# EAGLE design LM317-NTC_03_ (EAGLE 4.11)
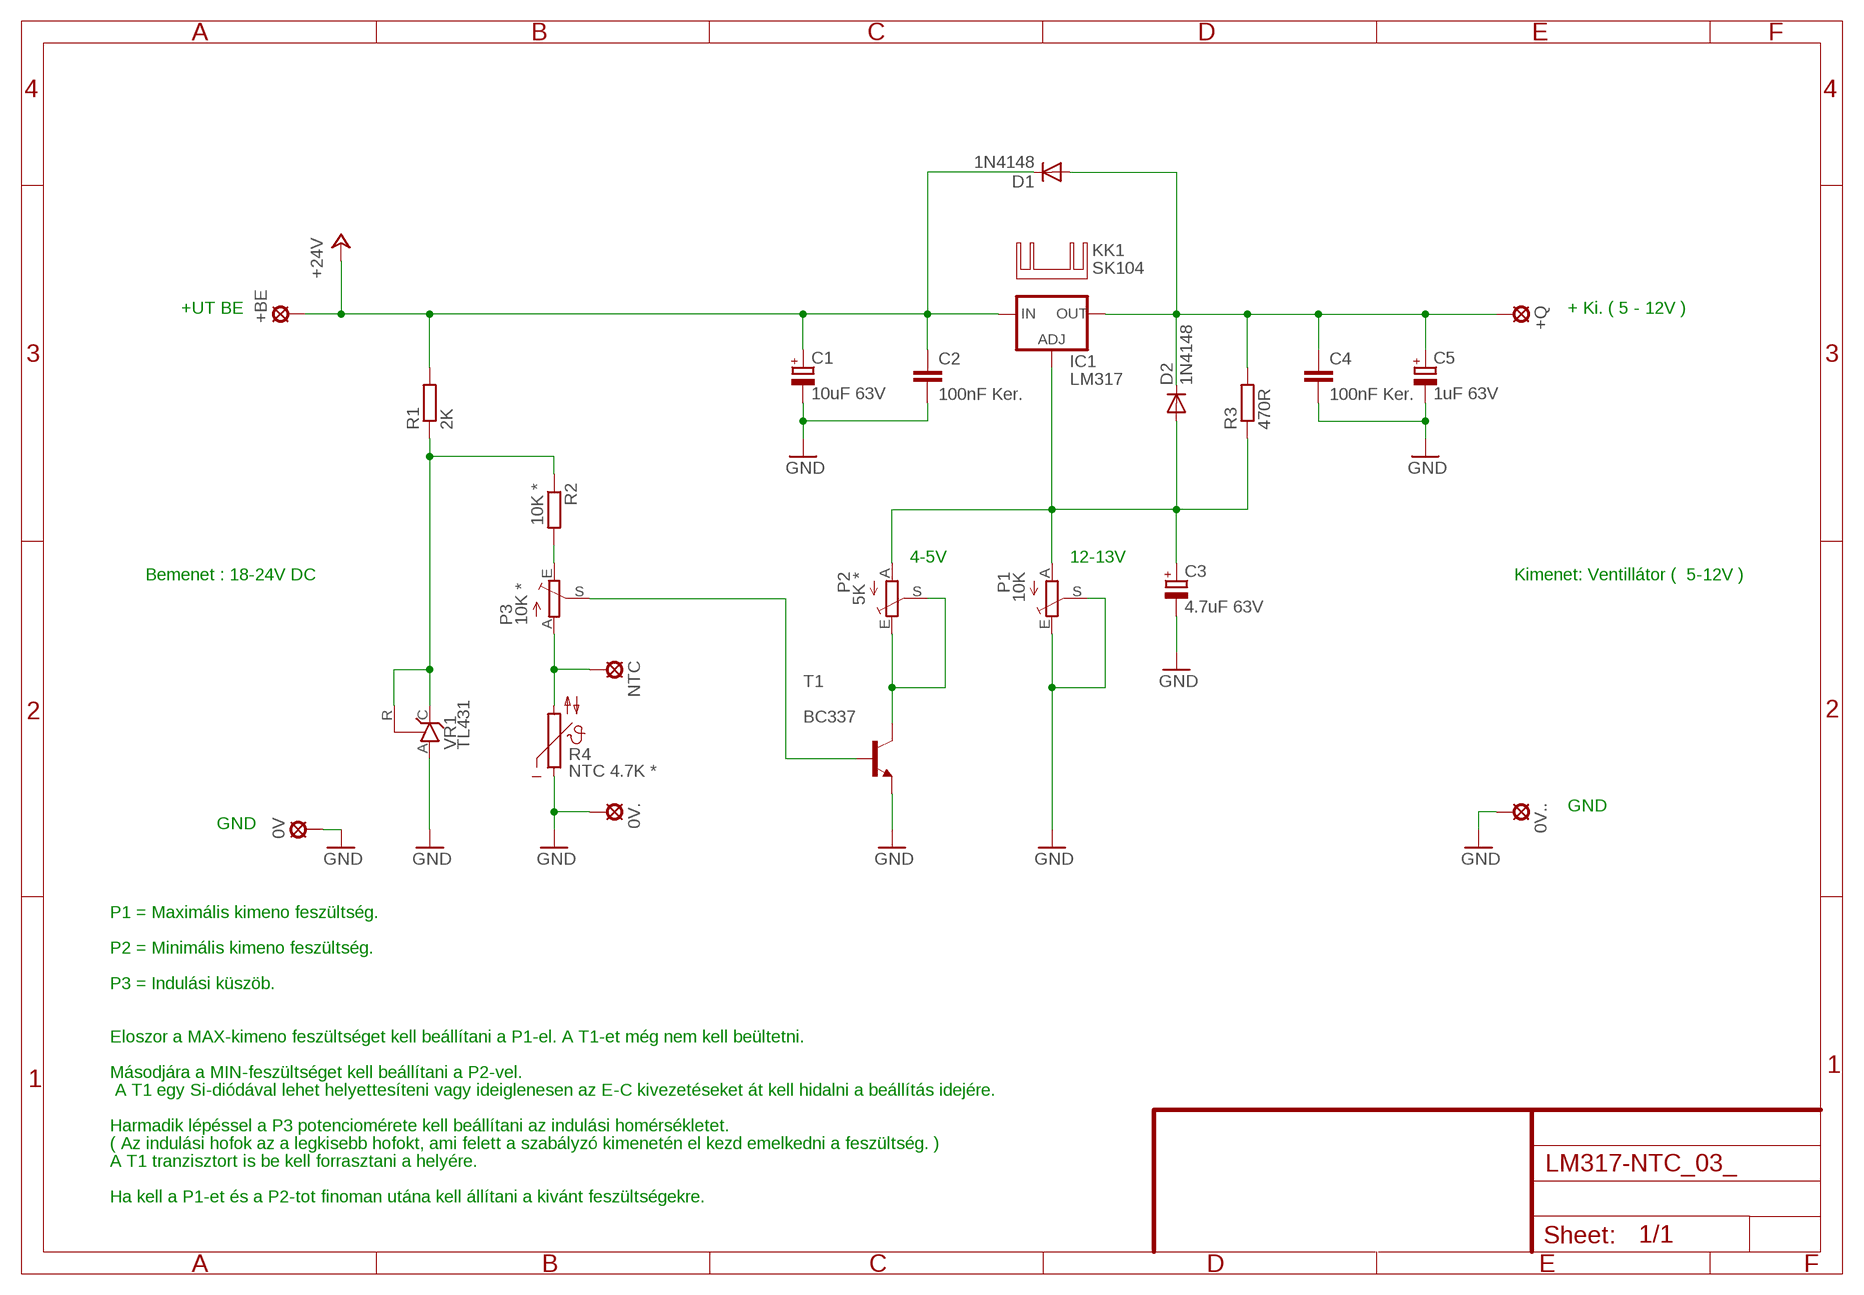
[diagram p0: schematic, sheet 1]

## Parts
0V  MCS10B  [MCS10B]
0V.  MCS10B  [MCS10B]
0V..  MCS10B  [MCS10B]
+BE  MCS10B  [MCS10B]
+Q  MCS10B  [MCS10B]
C1  10uF 63V  CPOL-EUE3.5-8  [E3,5-8]
C2  100nF Ker.  C-EU025-025X050  [C025-025X050]
C3  4.7uF 63V  CPOL-EUE3.5-8  [E3,5-8]
C4  100nF Ker.  C-EU025-025X050  [C025-025X050]
C5  1uF 63V  CPOL-EUE3.5-8  [E3,5-8]
D1  1N4148  [DO35-10]
D2  1N4148  [DO35-10]
IC1  LM317  LM317TS  [317TS]
KK1  SK104  [SK104]
NTC  MCS10B  [MCS10B]
P1  10K  TRIM_EU-B90P  [SP19L]
P2  5K *  TRIM_EU-B90P  [SP19L]
P3  10K *  TRIM_EU-B90P  [SP19L]
R1  2K  R-EU_0207/10  [0207/10]
R2  10K *  R-EU_0207/10  [0207/10]
R3  470R  R-EU_0207/10  [0207/10]
R4  NTC 4.7K *  NTC640-9  [N640]
T1  BC337  BC338-40-NPN-TO92-EBC  [TO92-EBC]
VR1  TL431  TL431CLP  [TO92-CLP]

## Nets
+24V: +BE.MP C1.+ C2.1 D1.C IC1.3(IN) R1.2
N$2: P3.E R2.2
N$3: NTC.MP P3.A R4.2
N$4: +Q.MP C4.1 C5.+ D1.A D2.C IC1.2(OUT) R3.2
N$5: P3.S T1.B
N$6: P2.E P2.S T1.C
N$7: C3.+ D2.A IC1.1(ADJ) P1.A P2.A R3.1
N$15: R1.1 R2.1 VR1.C VR1.R
N$16: 0V...MP 0V..MP 0V.MP C1.- C2.2 C3.- C4.2 C5.- P1.E P1.S R4.1 T1.E VR1.A ; supply symbol labelled GND

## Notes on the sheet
- +UT BE | + Ki. ( 5 - 12V )
- 4-5V | 12-13V
- Bemenet : 18-24V DC | Kimenet: Ventillátor (  5-12V )
- GND
- GND
- P1 = Maximális kimeno feszültség.
- P2 = Minimális kimeno feszültség.
- P3 = Indulási küszöb.
- Eloszor a MAX-kimeno feszültséget kell beállítani a P1-el. A T1-et még nem kell beültetni.
- Másodjára a MIN-feszültséget kell beállítani a P2-vel.
- A T1 egy Si-diódával lehet helyettesíteni vagy ideiglenesen az E-C kivezetéseket át kell hidalni a beállítás idejére.
- Harmadik lépéssel a P3 potenciomérete kell beállítani az indulási homérsékletet.
- ( Az indulási hofok az a legkisebb hofokt, ami felett a szabályzó kimenetén el kezd emelkedni a feszültség. )
- A T1 tranzisztort is be kell forrasztani a helyére.
- Ha kell a P1-et és a P2-tot finoman utána kell állítani a kivánt feszültségekre.

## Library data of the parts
0V 0V. 0V.. +BE +Q NTC = solpad:MCS10B: SOLDER PAD
C1 C3 C5 = rcl:CPOL-EU: POLARIZED CAPACITOR, European symbol
C2 C4 = rcl:C-EU: CAPACITOR, European symbol
D1 D2 = diode:1N4148: DIODE
IC1 = v-reg:LM317TS: VOLTAGE REGULATOR
KK1 = heatsink:SK104: HEATSINK
P1-P3 = pot:TRIM_EU-: POTENTIOMETER
R1-R3 = rcl:R-EU_: RESISTOR, European symbol
R4 = ptc-ntc:NTC640-9: PHILIPS NTC
T1 = transistor:*-NPN-: NPN Transistror
VR1 = v-reg:TL431CLP: VOLTAGE REGULATOR

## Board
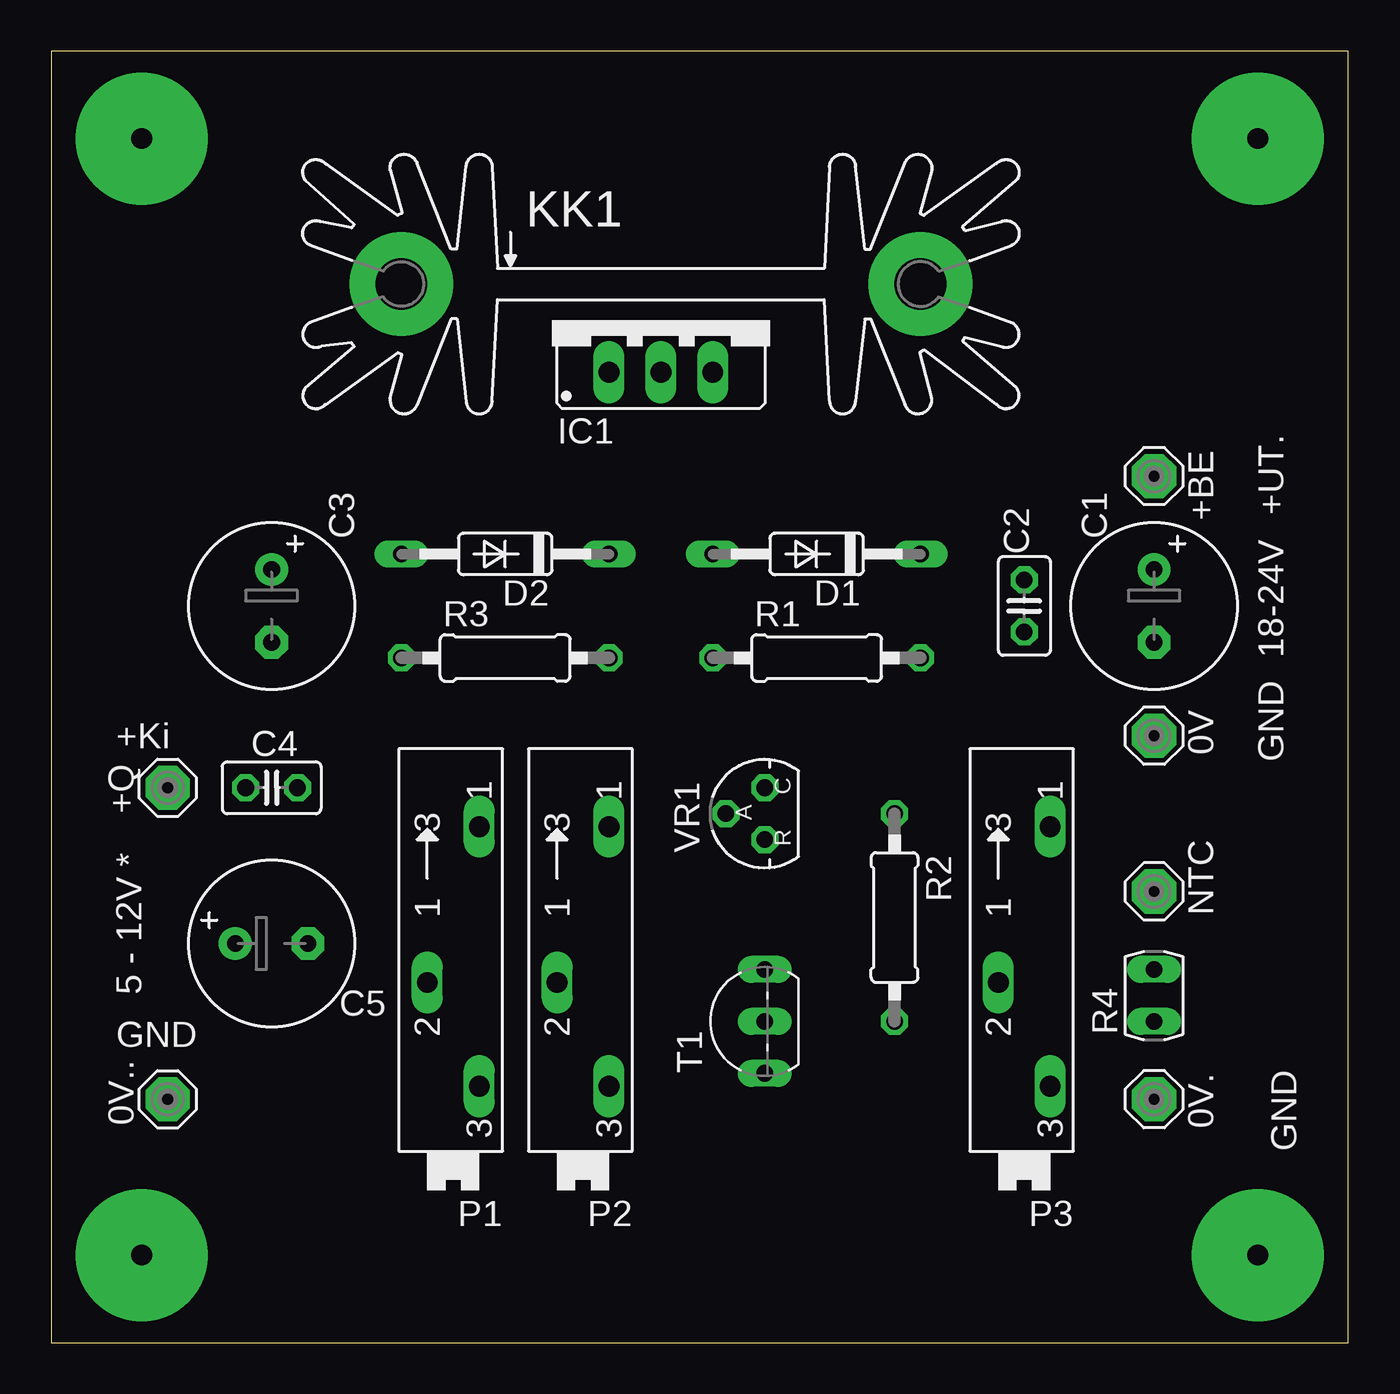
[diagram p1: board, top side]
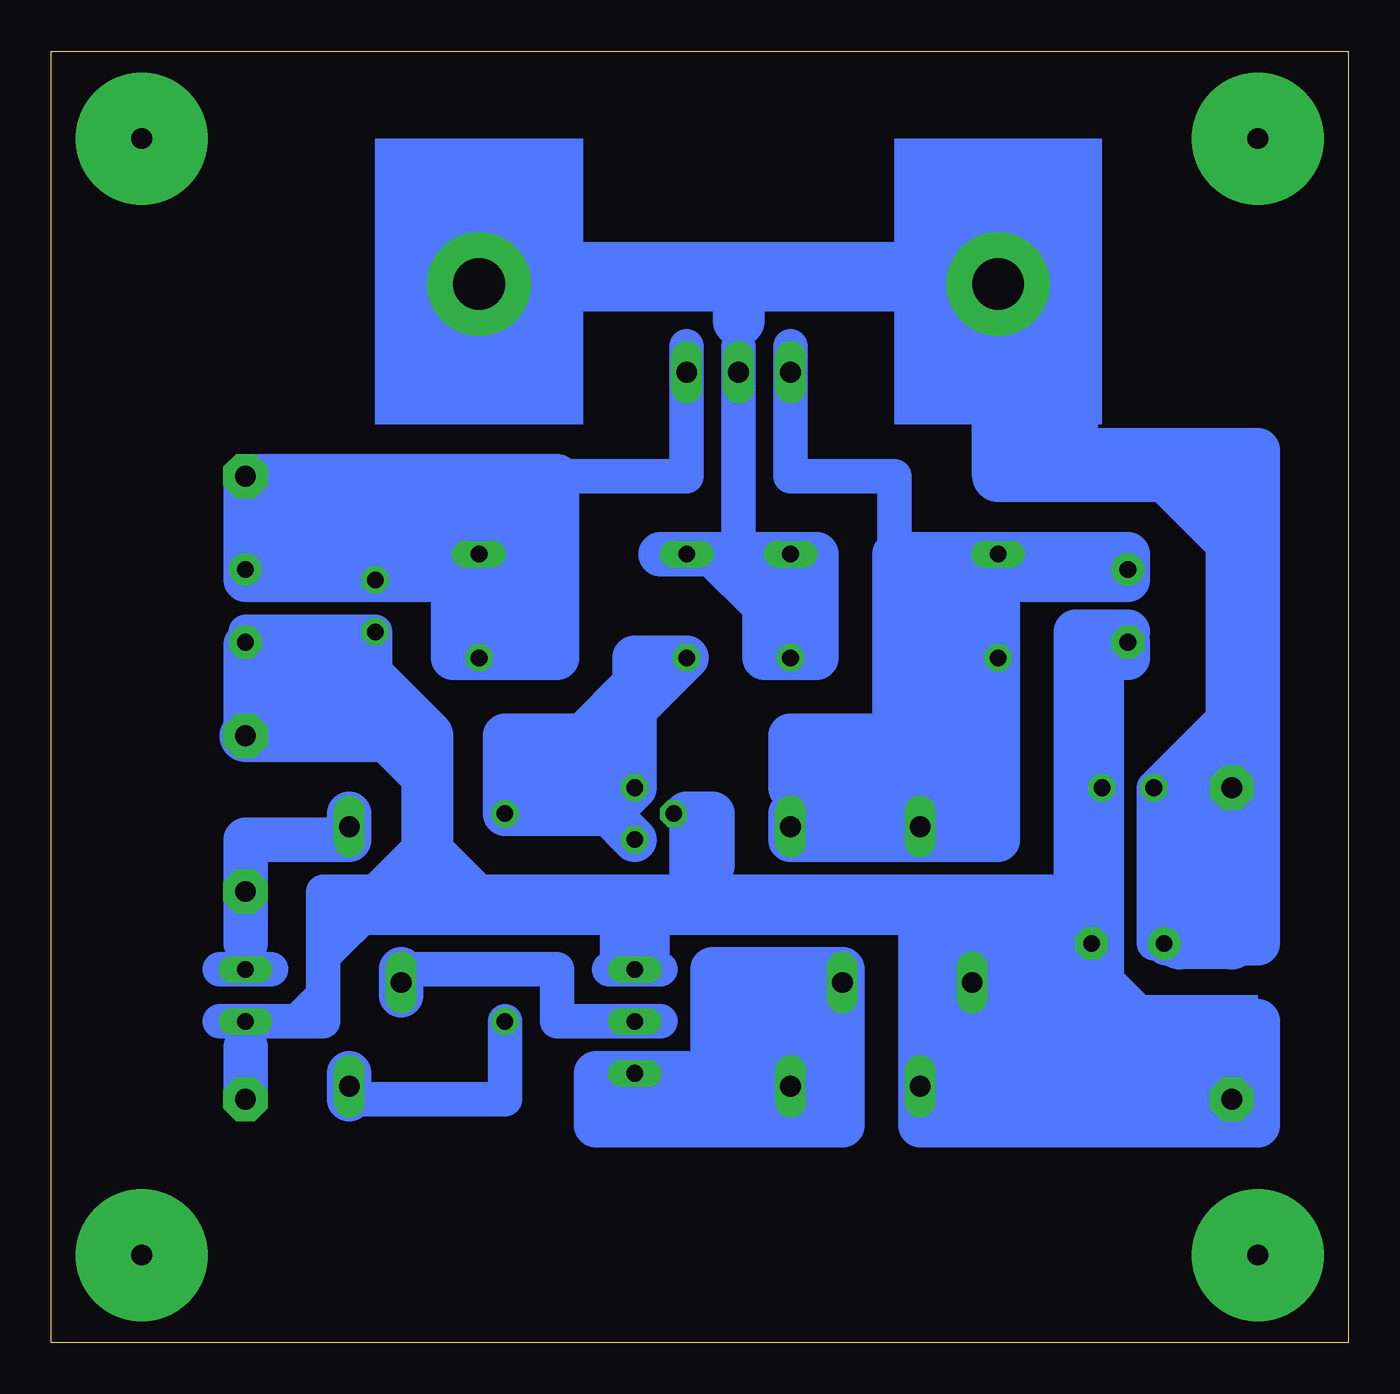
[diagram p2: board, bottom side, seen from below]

Size 63.48 x 63.17 mm. Coordinates in mm from the lower left corner, seen from the top.
Outline: 0,0 63.48,0 63.48,63.17 0,63.17 0,0
Copper layers (1*16): Top 0.035mm / dielectric 1.5mm / Bottom 0.035mm
Design rules "default": minimum track width 10mil, minimum drill 24mil, track to track 8mil, track to pad 8mil, pad to pad 8mil, via to via 8mil, smd to smd 8mil, copper to edge 40mil, drill to drill 8mil, minimum pad ring 10mil, minimum via ring 8mil, stop-mask expansion 4mil, vias tented up to drill 0mil, thermal gap 10mil

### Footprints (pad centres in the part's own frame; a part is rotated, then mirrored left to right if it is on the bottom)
MCS10B = drill 1.016 pad 2.159 octagon: MP 0,0
E3,5-8 = drill 0.813 pad 1.6 round: + -1.778,0 | drill 0.813 pad 1.6 octagon: - 1.778,0
C025-025X050 = drill 0.813 octagon: 1 -1.27,0; 2 1.27,0
DO35-10 = drill 0.813 long: A 5.08,0; C -5.08,0
317TS = drill 1.016 long: 1 -2.54,-2.54; 2 0,-2.54; 3 2.54,-2.54
SK104 = drill 2.54 pad 5.08 round: A2,5 -12.7,-0.762; B2,5 12.7,-0.762
SP19L = drill 1.016 long: A 5.715,-1.27; E -6.985,-1.27; S -1.905,1.27
0207/10 = drill 0.813 octagon: 1 -5.08,0; 2 5.08,0
N640 = drill 0.813 long: 1 -1.27,0; 2 1.27,0
TO92-EBC = drill 0.813 long: B 0,-1.27; C -2.54,-1.27; E 2.54,-1.27
TO92-CLP = drill 0.813 octagon: A 0,1.905; C 1.27,0; R -1.27,0

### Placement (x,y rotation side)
0V  53.97,29.68 270 top
0V.  53.97,11.9 270 top
0V..  5.71,11.9 90 top
+BE  53.97,42.38 270 top
+Q  5.71,27.14 90 top
C1  53.97,36.03 270 top
C2  47.62,36.03 270 top
C3  10.79,36.03 270 top
C4  10.79,27.14 0 top
C5  10.79,19.52 0 top
D1  37.46,38.57 180 top
D2  22.22,38.57 180 top
IC1  29.84,50 0 top
KK1  29.84,52.54 0 top
NTC  53.97,22.06 270 top
P1  19.68,19.52 90 top
P2  26.03,19.52 90 top
P3  47.62,19.52 90 top
R1  37.46,33.49 0 top
R2  41.27,20.79 270 top
R3  22.22,33.49 0 top
R4  53.97,16.98 90 top
T1  33.65,15.71 90 top
VR1  34.92,25.87 90 top

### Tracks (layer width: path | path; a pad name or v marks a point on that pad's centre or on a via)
+24V
  Bottom 0.406: 43.81,38.57 47.62,38.57 | 53.97,37.3 C1.+ 53.97,38.57
  Bottom 1.676: 32.38,48.73 IC1.3 32.38,42.38 38.73,42.38 | 41.27,42.38 42.54,42.38 42.54,41.11 D1.C | 43.81,38.57 D1.C | R1.2 42.54,37.3 | D1.C 47.62,38.57 | C2.1 47.62,38.57 | 47.62,38.57 53.97,38.57 | D1.C 42.54,37.3 | 42.54,37.3 53.97,37.3
  Bottom 2.184: R1.2 D1.C 41.27,38.57 | 41.27,42.38 +BE.MP 53.97,38.57 53.97,37.3 41.27,37.3 | 41.27,37.3 41.27,42.38 | 41.27,42.38 42.54,41.11 43.81,41.11 | 43.81,41.11 52.7,41.11 52.7,39.84 43.81,39.84 43.81,33.49 41.27,33.49 | 41.27,33.49 41.27,37.3 | 41.27,42.38 38.73,42.38 | 38.73,42.38 42.54,42.38 43.81,41.11 | 38.73,42.38 38.73,33.49 40,33.49 | 41.27,33.49 40,33.49 | 40,33.49 40,41.11
N$1
  Bottom 2.184: 34.28,20.15 34.28,18.88
N$2
  Bottom 0.406: 48.89,13.17 P3.E 48.89,11.9
  Bottom 1.676: R2.2 41.27,11.9 48.89,11.9
  Bottom 2.184: 48.89,13.17 48.89,11.9
N$3
  Bottom 0.406: P3.A 48.89,24.6
  Bottom 1.676: R4.2 52.7,18.25 | 55.24,18.25 R4.2 | R4.2 53.97,19.52 NTC.MP 53.97,24.6 50.16,24.6
  Bottom 2.184: 48.89,25.87 48.89,24.6 | 50.16,24.6 48.89,24.6 | 48.89,24.6 53.97,24.6 53.97,19.52
N$4
  Bottom 0.406: IC1.2 29.84,38.57 D1.A | D2.C R3.2 | 17.14,52.54 29.84,52.54 | 29.84,50 29.84,48.73
  Bottom 1.676: 4.44,28.41 4.44,27.14 | 4.44,27.14 4.44,25.87 | 4.44,19.52 4.44,27.14 | 4.44,27.14 4.44,43.65 | 15.87,43.65 15.87,44.92 | 29.84,38.57 D2.C R3.2 | 29.84,38.57 33.65,38.57 | IC1.2 29.84,48.73 29.84,38.57 | +Q.MP C4.1 | 9.52,19.52 C5.+ | C4.1 9.52,19.52 | 5.71,30.95 8.25,28.41 | 8.25,28.41 C4.1 | 6.98,28.41 8.25,28.41 | 5.71,19.52 8.88,19.52 9.52,19.52 | 9.52,42.38 5.71,38.57 5.71,39.84 8.25,42.38
  Bottom 2.184: 15.87,43.65 4.44,43.65 4.44,19.52 8.88,19.52 | D2.C 33.65,38.57 31.11,38.57 28.57,36.03 | D2.C 26.03,38.57 26.03,33.49 28.57,33.49 28.57,36.03 | D2.C R3.2 | 28.57,36.03 28.57,37.3
  Bottom 2.54: 29.84,50 29.84,52.54 42.54,52.54 | 42.54,52.54 42.54,51.27 | 42.54,52.54 17.14,52.54 17.14,42.38 9.52,42.38 8.25,42.38 5.71,42.38 5.71,38.57 5.71,30.95 +Q.MP | +Q.MP 8.25,27.14 8.25,19.52 5.71,19.52 +Q.MP
N$5
  Bottom 0.406: 46.35,18.25 P3.S 46.35,16.98
  Bottom 1.676: 46.35,18.25 38.73,18.25 38.73,15.71 T1.B 33.65,15.71
  Bottom 2.184: 46.35,18.25 46.35,16.98
N$6
  Bottom 0.406: 24.76,16.98 P2.S | 27.3,13.17 P2.E 27.3,10.63
  Bottom 1.676: 24.76,10.63 27.3,10.63 | 27.3,13.17 27.3,10.63 | 27.3,10.63 31.11,10.63 | 34.92,10.63 T1.C | T1.C 33.65,13.17 | T1.C 36.19,13.17 | 36.83,10.63 35.55,11.9 34.28,11.9 | 32.38,11.9 34.28,11.9 | 34.28,11.9 35.55,10.63 36.19,10.63
  Bottom 2.184: 34.28,10.63 31.11,10.63 31.11,18.25 24.76,18.25 24.76,16.98 24.76,10.63 34.28,10.63 | 34.92,10.63 34.28,10.63 | 34.28,10.63 36.83,10.63 36.83,13.17 32.38,13.17
N$7
  Bottom 0.406: 27.3,46.19 IC1.1 | D2.A R3.1 | C3.+ 10.79,38.57 | 12.06,38.57 15.87,38.57 | P1.A 21.59,25.87 | 21.59,25.87 22.22,25.87 | 27.3,24.6 P2.A 27.3,25.87 | 21.59,25.87 20.95,25.87
  Bottom 1.676: 10.79,37.3 12.06,37.3 12.06,38.57 10.79,38.57 15.87,38.57 | D2.A R3.1 17.14,25.87 | 19.68,25.87 20.95,25.87 | 20.95,24.6 20.95,25.87 | 20.95,25.87 22.22,25.87 | 22.22,38.57 22.22,42.38 27.3,42.38 27.3,46.19 27.3,48.73
  Bottom 2.184: 17.14,24.6 27.3,24.6 27.3,25.87 22.22,25.87 | 22.22,25.87 19.68,25.87 | 18.41,25.87 17.14,25.87 17.14,24.6 | 17.14,24.6 D2.A | D2.A 22.22,38.57 22.22,25.87 | 15.87,38.57 D2.A | D2.A 10.79,38.57 10.79,37.3 15.87,37.3 | 22.22,25.87 20.95,27.14 20.95,37.3 19.68,37.3 19.68,25.87 | 19.68,25.87 18.41,25.87 | 18.41,25.87 18.41,37.3
N$8
  Bottom 2.184: 14.6,44.92 13.33,44.92
N$9
  Bottom 1.676: 22.22,51.27 37.46,51.27
N$10  (via drill 1.02 pad 6.45)
  other vias: 4.44,4.28
N$11  (via drill 1.02 pad 6.45)
  other vias: 59.05,4.28
N$12  (via drill 1.02 pad 6.45)
  other vias: 59.05,58.89
N$13  (via drill 1.02 pad 6.45)
  other vias: 4.44,58.89
N$14
  Bottom 2.184: 23.49,29.68 27.3,29.68 27.3,27.14 26.03,27.14 26.03,28.41 23.49,28.41 23.49,27.14 24.76,27.14
N$15
  Bottom 0.406: VR1.R VR1.C 34.92,25.87 36.19,25.87
  Bottom 2.184: 36.19,29.68 37.46,29.68 | 37.46,29.68 41.27,29.68 41.27,28.41 | 34.92,32.22 34.92,33.49 R1.1 34.92,30.95 | 34.92,32.22 34.92,30.95 | 34.92,30.95 VR1.C 36.19,25.87 | VR1.R 36.19,25.87 | 36.19,25.87 R2.1 41.27,28.41 | 41.27,28.41 36.19,28.41 36.19,27.14 40,27.14 | 37.46,29.68 34.92,32.22
N$16
  Bottom 0.406: 18.41,16.98 P1.S 18.41,20.79 | 11.55,33.49 C3.- 11.3,34.76 13.33,33.49 | 32.38,25.87 VR1.A | 13.33,22.06 13.33,20.79 13.33,20.28 C5.- | 32.38,20.79 20.95,20.79 P1.E 20.95,10.63 | 53.97,34.76 C1.- 53.97,34.12
  Bottom 1.676: 47.62,33.49 C2.2 53.97,34.76 53.97,34.12 53.97,33.49 | 0V.MP 53.97,33.49 | 53.97,33.49 47.62,33.49 | 47.62,33.49 47.62,32.22 47.62,29.68 45.08,27.14 | 45.08,22.06 45.08,20.79 | 50.16,18.88 50.16,16.98 | 50.16,16.98 50.16,15.71 51.43,15.71 | 51.43,15.71 R4.1 | R4.1 53.97,14.44 | R4.1 55.24,15.71 | 36.19,18.25 T1.E | 33.65,18.25 T1.E | T1.E 34.92,20.79 | 34.92,20.79 45.08,20.79 | 32.38,25.87 32.38,20.79 34.92,20.79 | 34.92,20.79 20.95,20.79 18.41,20.79 | 18.41,20.79 13.33,20.79 12.06,20.79 | 18.41,20.79 18.41,16.98 | 20.95,10.63 6.98,10.63 | 6.98,10.63 0V...MP | 12.06,20.79 12.06,19.52 | 13.33,19.52 13.33,22.06 | 12.06,20.79 12.06,22.06 13.33,22.06 | 13.33,22.06 42.54,22.06 | 42.54,22.06 45.08,22.06 | 47.62,22.06 50.16,22.06 50.16,20.79 | 6.98,10.63 4.44,10.63 | 45.08,22.06 47.62,22.06 | 47.62,22.06 45.08,24.6 42.54,22.06 | 45.08,20.79 50.16,20.79 | 50.16,20.79 50.16,18.88 | 50.16,18.88 47.62,21.43 | 50.16,16.98 51.43,15.71
  Bottom 2.184: 10.79,34.76 13.33,34.76 13.33,33.49 | 32.38,25.87 31.11,25.87 31.11,23.33 | 12.06,33.49 C3.- 10.79,33.49 11.55,33.49 12.06,33.49 | 12.06,33.49 13.33,33.49 | 13.33,33.49 13.33,27.14 | C4.2 13.33,27.14 | 13.33,27.14 13.33,22.06 | 13.33,19.52 12.06,19.52 | 12.06,19.52 12.06,22.06 12.06,32.22 | 12.06,19.52 12.06,18.25 | 12.06,18.25 12.06,16.98 | 20.95,20.79 20.95,10.63 4.44,10.63 4.44,15.71 | 0V..MP 53.97,14.44 | 53.97,34.12 0V.MP | 12.06,18.25 12.06,17.61 10.15,15.71
  Bottom 2.54: 0V.MP 47.62,29.68 45.08,29.68 | 45.08,29.68 45.08,27.14 45.08,24.6 45.08,22.06 | 45.08,29.68 47.62,32.22
N$17
  Bottom 2.184: 35.55,20.15 35.55,18.88
(copper drawn outside any net)
  shapes: Bottom area x12

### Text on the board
tPlace: +UT. | 18-24V | +Ki | GND | 5 - 12V * | GND | GND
